// Mitsubishi GX Works2 project: 步进电机例程   PLC: FX1S

PROGRAM MAIN
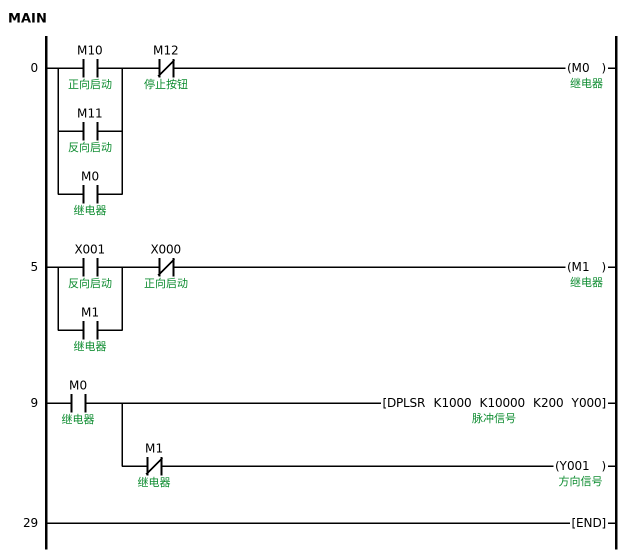
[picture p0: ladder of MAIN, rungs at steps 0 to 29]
0     LD      M10  ; 正向启动
      OR      M11  ; 反向启动
      OR      M0  ; 继电器
      ANI     M12  ; 停止按钮
      OUT     M0  ; 继电器
5     LD      X001  ; 反向启动
      OR      M1  ; 继电器
      ANI     X000  ; 正向启动
      OUT     M1  ; 继电器
9     LD      M0  ; 继电器
      DPLSR   K1000 K10000 K200 Y000  ; 脉冲信号
      ANI     M1  ; 继电器
      OUT     Y001  ; 方向信号
29    END
END_PROGRAM

// device comments not shown above
X002  ; 停止按钮
